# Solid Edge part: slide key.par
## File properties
Title: Slide Key
Author: Abhinav Rai
Template: Normal.par
Last saved by: CADCIM
Revision: 8
Application: Solid Edge
Density: 0.0000078 kg/mm^3
Accuracy: 0.01
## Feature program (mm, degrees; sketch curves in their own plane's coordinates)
sketch for "unnamed Protrusion 1" plane through (0, 0, 0) normal (0, -1, 0) x-axis (1, 0, 0)
  line (-30.0365, -12.1146) -> (28.6883, -12.1146)
  line (28.6883, -12.1146) -> (28.6883, -17.6629)
  line (1.9812, -17.6629) -> (28.6883, -17.6629)
  line (1.9812, -13.3979) -> (1.9812, -17.6629)
  line (-1.9812, -13.3979) -> (1.9812, -13.3979)
  line (-1.9812, -17.6629) -> (-1.9812, -13.3979)
  line (-30.0365, -17.6629) -> (-1.9812, -17.6629)
  line (-30.0365, -17.6629) -> (-30.0365, -12.1146)
extrude "unnamed Protrusion 1" add finite 4.7244 along +normal
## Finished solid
Body 1: solid body, 10 faces, 24 edges, 16 vertices.
  Faces by surface: plane 10
  Edges by curve: line 24
Bounding box of the edges (mm): 58.725 x 4.724 x 5.548, from (-30.0365, -4.7244, -17.6629) to (28.6883, 0, -12.1146).
Planar faces by outward normal: +x 2, +y 1, +z 1, -x 2, -y 1, -z 3
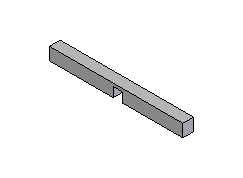
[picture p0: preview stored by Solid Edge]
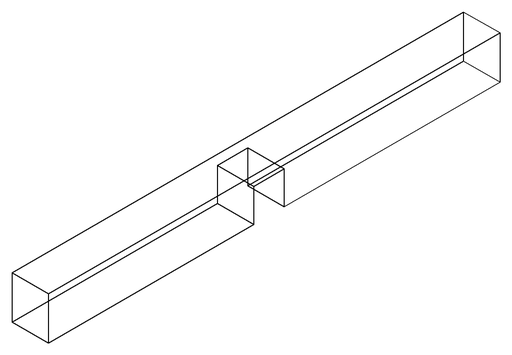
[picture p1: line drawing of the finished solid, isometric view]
